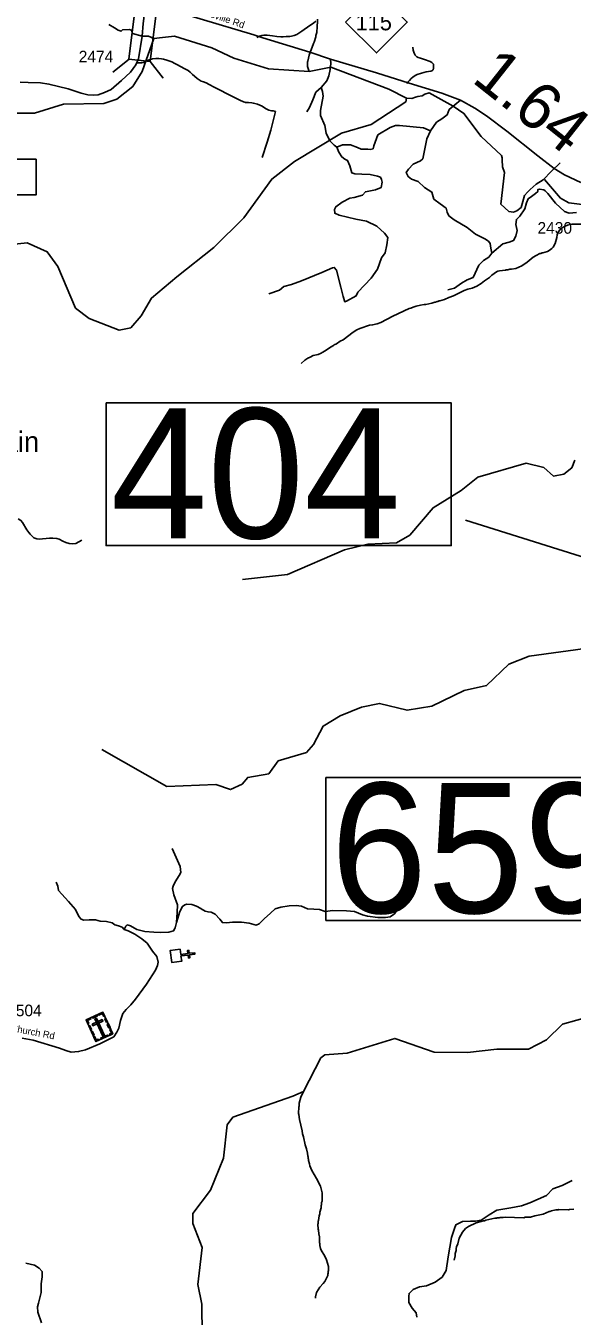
# Model space of a CAD drawing. Extents: x 1248224 to 1454986, y 825081 to 985870.
# Drawn here: x 1388229 to 1394113, y 851257 to 865144 of the extents above; entities that cross this region are included whole.
import ezdxf

# ---------------------------------------------------------------- set-up
doc = ezdxf.new("R2010")
doc.units = 0
for name, color, linetype in [('Exist Cultural Cemetery CELL', 7, 'Continuous'), ('Exist Cultural Church CELL', 7, 'Continuous'), ('Exist Geographical Mountain Summit Label', 7, 'Continuous'), ('Exist Hydrographic Creek Single Shore', 7, 'Continuous'), ('Exist Hydrographic Misc Water Feature', 7, 'Continuous'), ('Exist Road Non-System Type 51', 7, 'Continuous'), ('Exist Road Primary NC Attributed', 7, 'Continuous'), ('Exist Road Primary NC Label', 7, 'Continuous'), ('Exist Road Primary NC Mileage Hundredths English Label', 7, 'Continuous'), ('Exist Road Primary NC Shield CELL', 7, 'Continuous'), ('Exist Road Primary NC Shield Number Label', 7, 'Continuous'), ('Exist Road Secondary Structure Standard Bridge CELL', 7, 'Continuous'), ('Exist Road Secondary Structure Standard Bridge Number Label', 7, 'Continuous'), ('Exist Road Secondary Type 41 Attributed', 7, 'Continuous'), ('Exist Road Secondary Type 51 Attributed', 7, 'Continuous'), ('Exist Road Secondary Type 51 Label', 7, 'Continuous'), ('Exist Road Secondary Type 51 Number Label', 7, 'Continuous')]:
    doc.layers.add(name, color=color, linetype=linetype)

msp = doc.modelspace()

# ---------------------------------------------------------------- linework, layer by layer
at = {"layer": 'Exist Cultural Cemetery CELL'}
for points in [[(1388878, 854445), (1389059, 854528), (1389166, 854297), (1388985, 854213)], [(1389077, 854489), (1389067, 854484), (1389054, 854513), (1389017, 854496), (1389012, 854506), (1389059, 854528)], [(1388897, 854405), (1388907, 854410), (1388893, 854439), (1388930, 854456), (1388926, 854466), (1388878, 854445)], [(1388928, 854338), (1388910, 854377), (1388920, 854382), (1388938, 854343)], [(1388944, 854400), (1388952, 854383), (1389059, 854432), (1389051, 854449)], [(1388946, 854476), (1388993, 854497), (1388998, 854487), (1388951, 854465)], [(1388990, 854464), (1388973, 854456), (1389058, 854272), (1389075, 854279)], [(1389098, 854417), (1389080, 854457), (1389090, 854462), (1389108, 854422)], [(1389125, 854358), (1389107, 854397), (1389118, 854402), (1389136, 854362)], [(1388956, 854277), (1388938, 854316), (1388948, 854321), (1388966, 854282)], [(1389015, 854227), (1389010, 854238), (1388990, 854228), (1388973, 854265), (1388963, 854260), (1388985, 854213)], [(1389033, 854248), (1389110, 854283), (1389114, 854273), (1389037, 854237)], [(1389136, 854283), (1389131, 854293), (1389151, 854303), (1389134, 854339), (1389144, 854344), (1389166, 854297)]]:
    msp.add_lwpolyline(points, close=True, dxfattribs=at)
at = {"layer": 'Exist Cultural Church CELL'}
msp.add_lwpolyline([(1389891, 855207), (1389898, 855150), (1389974, 855160), (1389970, 855192), (1389986, 855194), (1389990, 855162), (1390049, 855169), (1390051, 855154), (1389992, 855146), (1389996, 855114), (1389980, 855112), (1389976, 855144), (1389900, 855134), (1389908, 855077), (1389802, 855063), (1389785, 855193)], close=True, dxfattribs=at)
at = {"layer": 'Exist Hydrographic Creek Single Shore'}
for points in [[(1389124, 865159), (1389184, 865124), (1389225, 865097), (1389257, 865086), (1389269, 865100), (1389344, 865105), (1389367, 865096), (1389378, 865061), (1389481, 865034)], [(1389481, 865034), (1389551, 865033), (1389608, 865007)], [(1392330, 864365), (1392140, 864461), (1391513, 864701), (1391280, 864654), (1390844, 864680), (1390471, 864796), (1390231, 864909), (1389830, 865032), (1389702, 865019), (1389608, 865007)], [(1393800, 863488), (1393725, 863440), (1393659, 863381), (1393631, 863355), (1393598, 863319), (1393562, 863190), (1393517, 863153), (1393482, 863137), (1393430, 863147), (1393345, 863225), (1393385, 863564), (1393361, 863628), (1393359, 863702), (1393359, 863725), (1393352, 863748), (1393132, 863952), (1392947, 864202), (1392832, 864280), (1392574, 864422), (1392527, 864410), (1392498, 864392), (1392449, 864385), (1392427, 864378), (1392387, 864362), (1392330, 864365)], [(1387593, 862740), (1388245, 862809), (1388460, 862713), (1388573, 862553), (1388764, 862106), (1388912, 861994), (1389234, 861870), (1389360, 861893), (1389471, 862023), (1389584, 862214), (1389855, 862442), (1390254, 862759), (1390577, 863077), (1390878, 863494), (1391123, 863683), (1391630, 863988), (1391949, 864083), (1392321, 864325), (1392330, 864365)], [(1395767, 862708), (1395688, 862697), (1395598, 862647), (1395465, 862631), (1395139, 862791), (1395047, 862842), (1394808, 862986), (1394572, 863128), (1394371, 863209), (1394219, 863222), (1394078, 863241), (1393985, 863291), (1393815, 863490)], [(1389049, 857356), (1389749, 856958), (1390275, 856980), (1390433, 856925), (1390559, 856981), (1390619, 857055), (1390845, 857094), (1390948, 857233), (1391250, 857325), (1391326, 857409), (1391431, 857607), (1391616, 857718), (1391843, 857812), (1392036, 857851), (1392335, 857779), (1392603, 857823), (1392948, 857990), (1393191, 858044), (1393429, 858273), (1393648, 858360), (1394333, 858455)]]:
    msp.add_lwpolyline(points, dxfattribs=at)
at = {"layer": 'Exist Hydrographic Misc Water Feature'}
for points in [[(1391370, 865216), (1391368, 865112), (1391363, 865096), (1391363, 865072), (1391354, 865041), (1391353, 865025), (1391336, 864969), (1391328, 864953), (1391281, 864827), (1391267, 864763), (1391263, 864755), (1391262, 864707), (1391280, 864654)], [(1385074, 863890), (1385353, 864101), (1385412, 864117), (1385642, 864345), (1385806, 864595), (1385915, 864632), (1386006, 864623), (1386361, 864449), (1386603, 864444), (1386752, 864408), (1386917, 864287), (1387050, 864284), (1387361, 864386), (1387777, 864361), (1388124, 864203), (1388324, 864206), (1388635, 864301), (1389068, 864309), (1389211, 864355), (1389381, 864493), (1389484, 864652), (1389608, 865007)], [(1393800, 863488), (1393891, 863580), (1393983, 863670)], [(1391193, 861510), (1391234, 861547), (1391266, 861568), (1391291, 861580), (1391323, 861595), (1391379, 861607), (1391411, 861622), (1391420, 861630), (1391452, 861647), (1391509, 861686), (1391541, 861703), (1391550, 861711), (1391574, 861722), (1391615, 861749), (1391647, 861766), (1391753, 861846), (1391794, 861871), (1391826, 861886), (1391931, 861923), (1391963, 861926), (1392011, 861937), (1392052, 861950), (1392181, 862021), (1392359, 862101), (1392375, 862104), (1392400, 862116), (1392432, 862127), (1392480, 862137), (1392520, 862145), (1392536, 862144), (1392601, 862159), (1392633, 862170), (1392641, 862169), (1392657, 862177), (1392665, 862177), (1392682, 862184), (1392689, 862184), (1392738, 862199), (1392786, 862222), (1392835, 862239), (1392948, 862294), (1392989, 862309), (1393037, 862320), (1393085, 862342), (1393134, 862371), (1393167, 862398), (1393224, 862437), (1393248, 862460), (1393297, 862495), (1393313, 862503), (1393330, 862508), (1393394, 862515), (1393402, 862518), (1393418, 862518), (1393442, 862525), (1393458, 862525), (1393506, 862534), (1393571, 862562), (1393628, 862599), (1393693, 862653), (1393726, 862674), (1393766, 862693), (1393774, 862693), (1393790, 862701), (1393798, 862700), (1393847, 862717), (1393863, 862725), (1393894, 862748), (1393906, 862762), (1393929, 862801), (1393946, 862865), (1393951, 862896), (1393958, 862918), (1393964, 862928), (1393980, 862950), (1394005, 862969), (1394029, 862985), (1394062, 862998), (1394110, 863009), (1394222, 863008)], [(1390563, 859184), (1391048, 859240), (1391662, 859503), (1391913, 859564), (1392222, 859580), (1392365, 859663), (1392614, 859957), (1392917, 860144), (1393096, 860288), (1393616, 860436), (1393807, 860392), (1393913, 860298), (1394022, 860319), (1394107, 860386), (1394142, 860468)], [(1390091, 850947), (1390127, 851054), (1390126, 851386), (1390080, 851597), (1390130, 851997), (1390027, 852255), (1390029, 852363), (1390218, 852612), (1390358, 852957), (1390399, 853317), (1390459, 853398), (1391106, 853625), (1391219, 853676), (1391406, 854036), (1391449, 854071), (1391691, 854089), (1392203, 854246), (1392625, 854097), (1392984, 854096), (1393301, 854132), (1393643, 854132), (1393837, 854230), (1394007, 854400), (1394317, 854486)], [(1391350, 851449), (1391350, 851465), (1391361, 851513), (1391397, 851570), (1391432, 851607), (1391448, 851631), (1391480, 851694), (1391480, 851710), (1391485, 851718), (1391485, 851736), (1391489, 851750), (1391490, 851790), (1391468, 851862), (1391445, 851911), (1391414, 851960), (1391403, 851984), (1391396, 852016), (1391396, 852040), (1391392, 852048), (1391390, 852112), (1391383, 852144), (1391380, 852184), (1391376, 852192), (1391373, 852248), (1391377, 852256), (1391378, 852280), (1391382, 852288), (1391387, 852336), (1391396, 852360), (1391396, 852376), (1391409, 852424), (1391410, 852447), (1391414, 852455), (1391415, 852481), (1391419, 852495), (1391421, 852583), (1391403, 852656), (1391361, 852737), (1391309, 852826), (1391288, 852874), (1391285, 852898), (1391274, 852931), (1391274, 852947), (1391270, 852955), (1391271, 852971), (1391267, 852979), (1391264, 853011), (1391253, 853059), (1391238, 853100), (1391220, 853188), (1391209, 853220), (1391205, 853252), (1391176, 853373), (1391170, 853429), (1391166, 853437), (1391168, 853509), (1391172, 853517), (1391173, 853549), (1391190, 853613), (1391219, 853676)], [(1392842, 851860), (1392854, 851908), (1392854, 851932), (1392863, 851963), (1392863, 851987), (1392868, 852003), (1392881, 852035), (1392896, 852096), (1392930, 852162), (1392965, 852199), (1392997, 852222), (1393078, 852262), (1393159, 852284), (1393167, 852284), (1393183, 852291), (1393280, 852313), (1393296, 852312), (1393304, 852316), (1393328, 852316), (1393336, 852319), (1393368, 852319), (1393392, 852322), (1393592, 852317), (1393608, 852321), (1393664, 852323), (1393712, 852338), (1393801, 852356), (1393865, 852382), (1393873, 852382), (1393890, 852390), (1393938, 852400), (1393962, 852400), (1393970, 852404), (1394074, 852401), (1394082, 852405), (1394130, 852408)]]:
    msp.add_lwpolyline(points, dxfattribs=at)
at = {"layer": 'Exist Road Non-System Type 51'}
for points in [[(1390716, 865020), (1390744, 865032), (1390769, 865039), (1390791, 865043), (1390827, 865044), (1390887, 865037), (1390931, 865030), (1390974, 865027), (1391002, 865027), (1391033, 865028), (1391069, 865029), (1391091, 865033), (1391119, 865040), (1391147, 865052), (1391202, 865085), (1391289, 865149), (1391326, 865174), (1391352, 865194)], [(1390918, 864222), (1390894, 864228), (1390876, 864231), (1390845, 864237), (1390831, 864244), (1390823, 864248), (1390809, 864256), (1390773, 864279), (1390749, 864289), (1390724, 864300), (1390696, 864308), (1390678, 864313), (1390664, 864315), (1390626, 864320), (1390594, 864320), (1390588, 864321), (1390574, 864325), (1390534, 864344), (1390392, 864415), (1390330, 864450), (1390259, 864485), (1390204, 864514), (1390170, 864529), (1390142, 864540), (1390118, 864550), (1390097, 864563), (1390087, 864569), (1390073, 864579), (1390047, 864602), (1390024, 864622), (1390000, 864647), (1389977, 864665), (1389935, 864686), (1389862, 864723), (1389834, 864738), (1389800, 864755), (1389749, 864774), (1389713, 864784), (1389689, 864789), (1389661, 864791), (1389631, 864792), (1389595, 864789), (1389559, 864780), (1389534, 864770), (1389508, 864755), (1389498, 864751), (1389480, 864747), (1389474, 864747), (1389430, 864746)], [(1392395, 864915), (1392402, 864882), (1392408, 864862), (1392416, 864842), (1392423, 864828), (1392433, 864816), (1392441, 864810), (1392453, 864805), (1392479, 864797), (1392524, 864782), (1392582, 864761), (1392602, 864750), (1392610, 864744), (1392618, 864732), (1392619, 864722), (1392619, 864698), (1392619, 864690), (1392614, 864672), (1392608, 864664), (1392592, 864658), (1392540, 864649), (1392490, 864636), (1392445, 864619), (1392421, 864608), (1392395, 864590), (1392378, 864577), (1392360, 864557), (1392348, 864541), (1392331, 864524)], [(1391511, 864786), (1391513, 864738), (1391508, 864673), (1391493, 864605), (1391471, 864553), (1391408, 864481), (1391352, 864429), (1391321, 864346), (1391284, 864266), (1391254, 864218)], [(1391408, 864481), (1391425, 864436), (1391432, 864389), (1391404, 864232), (1391404, 864180), (1391449, 864071), (1391465, 863988), (1391502, 863907), (1391550, 863859), (1391578, 863840), (1391641, 863862), (1391726, 863862), (1391802, 863835), (1391841, 863818), (1391911, 863816), (1391937, 863812), (1391969, 863822), (1391976, 863851), (1392019, 863970), (1392154, 864051), (1392211, 864071), (1392252, 864071), (1392513, 864047), (1392586, 864014)], [(1392586, 864014), (1392652, 864106), (1392710, 864145), (1392765, 864188), (1392787, 864243), (1392911, 864345)], [(1390918, 864222), (1390868, 864023), (1390830, 863893), (1390774, 863726)], [(1392586, 864014), (1392547, 863929), (1392506, 863714), (1392480, 863690), (1392399, 863655), (1392349, 863603), (1392325, 863566), (1392347, 863522), (1392382, 863494), (1392454, 863468), (1392521, 863405), (1392602, 863355), (1392623, 863280), (1392691, 863230), (1392756, 863181), (1392767, 863140), (1392784, 863100), (1392841, 863057), (1392980, 862974), (1393073, 862903), (1393115, 862881), (1393173, 862851), (1393210, 862825), (1393228, 862803), (1393237, 862751), (1393247, 862696), (1393215, 862655), (1393156, 862618), (1393108, 862568), (1393045, 862435), (1392980, 862411), (1392921, 862374), (1392847, 862322), (1392773, 862304)], [(1391578, 863840), (1391599, 863784), (1391632, 863734), (1391664, 863708), (1391695, 863695), (1391719, 863639), (1391740, 863562), (1391773, 863551), (1391847, 863549), (1391938, 863543), (1392017, 863525), (1392047, 863514), (1392058, 863491), (1392065, 863460), (1392056, 863406), (1391995, 863379), (1391886, 863358), (1391856, 863321), (1391764, 863297), (1391719, 863288), (1391634, 863247), (1391569, 863197), (1391553, 863166), (1391556, 863127), (1391603, 863105), (1391784, 863062), (1391899, 863042), (1392010, 862988), (1392093, 862914), (1392126, 862866), (1392117, 862787), (1392099, 862700), (1392058, 862646), (1392017, 862527), (1391947, 862427), (1391806, 862279), (1391788, 862238), (1391684, 862181), (1391664, 862175), (1391645, 862231), (1391623, 862333), (1391575, 862516), (1391551, 862545), (1391532, 862540), (1391416, 862490), (1391197, 862401), (1391092, 862362), (1391007, 862338), (1390960, 862301), (1390846, 862259)], [(1394159, 863134), (1394080, 863128), (1394030, 863145), (1393934, 863234), (1393850, 863339), (1393821, 863369), (1393806, 863378), (1393760, 863387), (1393741, 863382), (1393741, 863361), (1393717, 863339), (1393673, 863306), (1393639, 863284), (1393619, 863239), (1393602, 863173), (1393549, 863097), (1393512, 863060), (1393504, 863006), (1393521, 862940), (1393506, 862882), (1393482, 862834), (1393434, 862816), (1393367, 862797), (1393247, 862696)], [(1388148, 859839), (1388176, 859822), (1388194, 859800), (1388240, 859721), (1388261, 859691), (1388277, 859672), (1388314, 859635), (1388328, 859629), (1388348, 859623), (1388376, 859620), (1388410, 859622), (1388448, 859627), (1388484, 859630), (1388522, 859631), (1388564, 859626), (1388588, 859620), (1388628, 859599), (1388660, 859584), (1388695, 859572), (1388733, 859569), (1388767, 859574), (1388802, 859590), (1388832, 859607)], [(1389289, 855419), (1389306, 855456), (1389322, 855467), (1389357, 855457), (1389424, 855420), (1389512, 855396), (1389607, 855389), (1389685, 855386), (1389768, 855388), (1389820, 855404), (1389836, 855436), (1389851, 855495), (1389860, 855600), (1389864, 855683), (1389824, 855792), (1389809, 855859), (1389816, 855885), (1389836, 855933), (1389880, 855999), (1389897, 856032), (1389893, 856095), (1389805, 856290)], [(1389289, 855419), (1389266, 855444), (1389226, 855457), (1389189, 855469), (1389160, 855491), (1389098, 855503), (1389029, 855508), (1388979, 855523), (1388913, 855521), (1388855, 855520), (1388824, 855530), (1388801, 855558), (1388764, 855633), (1388690, 855719), (1388582, 855840), (1388573, 855886), (1388556, 855928)], [(1389851, 855495), (1389889, 855611), (1389917, 855667), (1389940, 855685), (1389965, 855692), (1390016, 855689), (1390067, 855671), (1390113, 855643), (1390117, 855640), (1390159, 855617), (1390192, 855608), (1390224, 855605), (1390270, 855583), (1390318, 855528), (1390347, 855493), (1390392, 855489), (1390454, 855496), (1390552, 855497), (1390635, 855486), (1390683, 855473), (1390709, 855464), (1390741, 855479), (1390797, 855533), (1390865, 855594), (1390916, 855641), (1390976, 855658), (1391065, 855673), (1391141, 855678), (1391197, 855670), (1391261, 855642), (1391329, 855636), (1391392, 855634), (1391452, 855613), (1391535, 855624), (1391684, 855620), (1391769, 855612), (1391853, 855577), (1391908, 855562), (1392020, 855549), (1392104, 855548), (1392151, 855554), (1392201, 855588), (1392225, 855624), (1392244, 855687)], [(1389310, 854558), (1389361, 854609), (1389410, 854670), (1389529, 854830), (1389625, 854980), (1389649, 855031), (1389653, 855066), (1389639, 855127), (1389595, 855185), (1389536, 855272), (1389479, 855318), (1389405, 855368), (1389333, 855403), (1389289, 855419)], [(1392438, 851248), (1392431, 851294), (1392389, 851342), (1392353, 851404), (1392353, 851473), (1392357, 851502), (1392402, 851545), (1392467, 851571), (1392545, 851584), (1392637, 851623), (1392712, 851675), (1392754, 851747), (1392777, 851894), (1392813, 852102), (1392845, 852199), (1392861, 852241), (1392930, 852277), (1393018, 852280), (1393070, 852280), (1393132, 852290), (1393220, 852349), (1393301, 852397), (1393451, 852424), (1393568, 852446), (1393656, 852476), (1393835, 852557), (1393904, 852626), (1394005, 852665), (1394112, 852717)]]:
    msp.add_lwpolyline(points, dxfattribs=at)
at = {"layer": 'Exist Road Primary NC Attributed'}
msp.add_lwpolyline([(1394205, 863457), (1394030, 863540), (1393919, 863608), (1393744, 863745), (1393410, 864010), (1393191, 864174), (1393063, 864258), (1392911, 864345), (1392709, 864419), (1392359, 864527), (1392005, 864639), (1391511, 864786), (1391286, 864860), (1390781, 865014), (1390684, 865046), (1389529, 865392)], dxfattribs=at)
at = {"layer": 'Exist Road Primary NC Shield CELL'}
msp.add_lwpolyline([(1391671, 865185), (1392004, 865518), (1392337, 865185), (1392004, 864852)], close=True, dxfattribs=at)
at = {"layer": 'Exist Road Secondary Structure Standard Bridge CELL'}
for p, q in [((1389344, 864786), (1389166, 864645)), ((1389568, 864759), (1389709, 864581))]:
    msp.add_line(p, q, dxfattribs=at)
msp.add_lwpolyline([(1389628, 865251), (1389569, 864759), (1389340, 864786), (1389398, 865278)], close=True, dxfattribs=at)
at = {"layer": 'Exist Road Secondary Structure Standard Bridge Number Label'}
for points in [[(1387411, 863709), (1388340, 863709), (1388340, 863324), (1387411, 863324)], [(1389094, 861086), (1392810, 861086), (1392810, 859550), (1389094, 859550)], [(1391460, 857053), (1395176, 857053), (1395176, 855516), (1391460, 855516)]]:
    msp.add_lwpolyline(points, close=True, dxfattribs=at)
msp.add_lwpolyline([(1400604, 858141), (1396497, 858716), (1392964, 859825)], dxfattribs=at)
at = {"layer": 'Exist Road Secondary Type 41 Attributed'}
for points in [[(1388189, 854248), (1388309, 854229), (1388593, 854140), (1388662, 854117), (1388719, 854100), (1388798, 854105), (1388872, 854124), (1389028, 854188), (1389176, 854265), (1389209, 854313), (1389231, 854358), (1389250, 854440), (1389274, 854514), (1389310, 854558)], [(1388399, 851186), (1388360, 851301), (1388357, 851357), (1388365, 851396), (1388393, 851511), (1388396, 851604), (1388407, 851682), (1388405, 851738), (1388374, 851772), (1388323, 851806), (1388228, 851828)]]:
    msp.add_lwpolyline(points, dxfattribs=at)
at = {"layer": 'Exist Road Secondary Type 51 Attributed'}
for points in [[(1389529, 865392), (1389520, 865353), (1389509, 865295), (1389507, 865281), (1389492, 865171), (1389481, 865034)], [(1389481, 865034), (1389444, 864789), (1389414, 864723), (1389357, 864645), (1389258, 864555), (1389147, 864459), (1389076, 864426), (1389009, 864401), (1388956, 864397), (1388897, 864403), (1388825, 864419), (1388685, 864466), (1388479, 864518), (1388387, 864532), (1388253, 864534), (1388169, 864539)]]:
    msp.add_lwpolyline(points, dxfattribs=at)

# ---------------------------------------------------------------- texts
at = {"layer": 'Exist Geographical Mountain Summit Label'}
msp.add_text('Pilot Mountain', height=220, dxfattribs=at).set_placement((1386509, 860558))
at = {"layer": 'Exist Road Primary NC Label'}
msp.add_text('Statesville Rd', height=75, rotation=341.083, dxfattribs=at).set_placement((1389990, 865315))
at = {"layer": 'Exist Road Primary NC Mileage Hundredths English Label'}
msp.add_text('1.64', height=500, rotation=321.6031, dxfattribs=at).set_placement((1393019, 864550))
at = {"layer": 'Exist Road Primary NC Shield Number Label'}
msp.add_text('115', height=175, dxfattribs=at).set_placement((1391781, 865096))
at = {"layer": 'Exist Road Secondary Structure Standard Bridge Number Label'}
for s, p in [('404', (1389144, 859629)), ('659', (1391510, 855596))]:
    msp.add_text(s, height=1400, dxfattribs=at).set_placement(p)
at = {"layer": 'Exist Road Secondary Type 51 Label'}
msp.add_text('Cherry Grove Church Rd', height=75, rotation=349.1442, dxfattribs=at).set_placement((1387444, 854444))
at = {"layer": 'Exist Road Secondary Type 51 Number Label'}
for s, p in [('2474', (1388799, 864751)), ('2430', (1393739, 862907)), ('2504', (1388029, 854485))]:
    msp.add_text(s, height=125, dxfattribs=at).set_placement(p)

doc.saveas('drawing.dxf')
